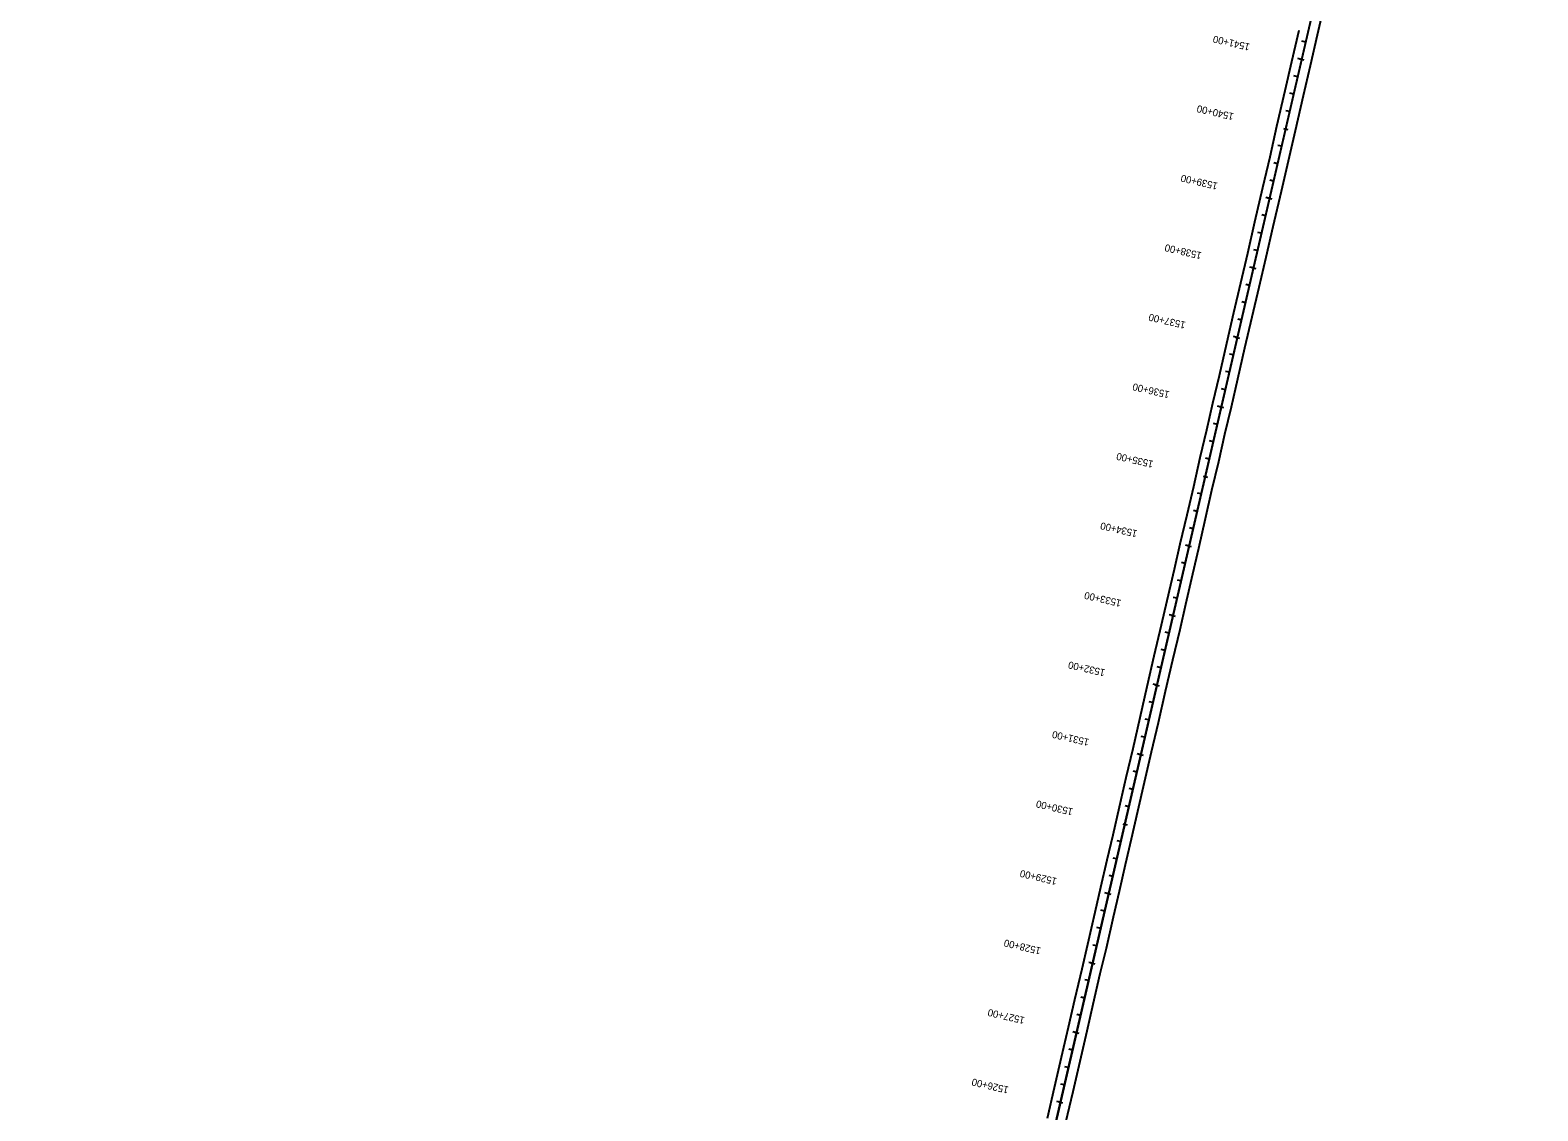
# Model space of a CAD drawing. Extents: x 21596470 to 21601942, y 8263806 to 8275912.
# Drawn here: x 21596601 to 21598714, y 8272882 to 8274396 of the extents above; entities that cross this region are included whole.
import ezdxf

# ---------------------------------------------------------------- set-up
doc = ezdxf.new("R2010")
doc.units = 0
for name, color, linetype in [('Level 1', 7, 'Continuous'), ('Level 20', 7, 'Continuous'), ('SurTxtLeaderLine', 7, 'Continuous'), ('SurTxtSurveyInformation', 7, 'Continuous'), ('wetNoteSoil', 7, 'Continuous')]:
    doc.layers.add(name, color=color, linetype=linetype)

msp = doc.modelspace()

# ---------------------------------------------------------------- linework, layer by layer
at = {"layer": 'Level 1'}
for p, q in [((21598383.4, 8274355.1), (21598378.1, 8274356.3)), ((21598357.9, 8274258.3), (21598363.9, 8274257)), ((21598338.3, 8274160.2), (21598333, 8274161.5)), ((21598315.8, 8274062.8), (21598310.5, 8274064)), ((21598293.3, 8273965.4), (21598287.9, 8273966.6)), ((21598270.7, 8273867.9), (21598265.4, 8273869.2)), ((21598245.2, 8273771.2), (21598251.2, 8273769.8)), ((21598225.6, 8273673.1), (21598220.3, 8273674.3)), ((21598203.1, 8273575.7), (21598197.8, 8273576.9)), ((21598180.6, 8273478.2), (21598175.3, 8273479.5)), ((21598158, 8273380.8), (21598152.7, 8273382)), ((21598132.5, 8273284.1), (21598138.5, 8273282.7)), ((21598113, 8273186), (21598107.6, 8273187.2)), ((21598090.4, 8273088.5), (21598085.1, 8273089.8)), ((21598067.9, 8272991.1), (21598062.6, 8272992.3)), ((21598045.3, 8272893.7), (21598040, 8272894.9))]:
    msp.add_line(p, q, dxfattribs=at)
at = {"layer": 'Level 20'}
for p, q in [((21596601.4, 8266652.3), (21598714.2, 8275785)), ((21596728.7, 8267202.6), (21598588.8, 8275242.6))]:
    msp.add_line(p, q, dxfattribs=at)
at = {"layer": 'SurTxtLeaderLine'}
msp.add_lwpolyline([(21598052.9, 8272865.9), (21598062.9, 8272908.8), (21598072.7, 8272951.2), (21598082.5, 8272993.7), (21598091.2, 8273031.1), (21598101.1, 8273074.3), (21598109.7, 8273109.6), (21598119.6, 8273153.6), (21598127.9, 8273189.4), (21598136.5, 8273226.8), (21598144.8, 8273262.7), (21598153.6, 8273301.9), (21598163, 8273342.3), (21598172.8, 8273384.6), (21598182.5, 8273425.8), (21598192.6, 8273469.8), (21598202.7, 8273513.7), (21598212.8, 8273556.3), (21598220.9, 8273591.8), (21598230.6, 8273634.4), (21598239.2, 8273670.4), (21598248.5, 8273711.9), (21598257.6, 8273751.3), (21598267, 8273791.7), (21598275.8, 8273830.1), (21598284.7, 8273868.1), (21598293.9, 8273907.3), (21598303.8, 8273951.1), (21598314.1, 8273994.4), (21598323.5, 8274036), (21598333.4, 8274078.2), (21598343.1, 8274120.8), (21598354.9, 8274170.3), (21598364.6, 8274213.1), (21598374.4, 8274255.4), (21598385.8, 8274304.5), (21598395.6, 8274346.4), (21598405.4, 8274389.7), (21598415.4, 8274432)], dxfattribs=at)
at = {"layer": 'SurTxtSurveyInformation'}
msp.add_lwpolyline([(21598027.1, 8272871.6), (21598036.9, 8272914.3), (21598046.9, 8272957), (21598056.6, 8272999), (21598065.6, 8273037.8), (21598075.6, 8273080.9), (21598083.6, 8273115.1), (21598093.8, 8273160.1), (21598102, 8273195.3), (21598110.9, 8273233.6), (21598118.9, 8273268.3), (21598128, 8273307.6), (21598137.5, 8273348.8), (21598146.9, 8273389.6), (21598166.8, 8273476.2), (21598176.7, 8273519.3), (21598187, 8273563), (21598195, 8273597.1), (21598204.9, 8273641), (21598213.2, 8273676.2), (21598222.7, 8273717), (21598232, 8273756.7), (21598241.2, 8273797.3), (21598250.3, 8273836), (21598258.8, 8273873.5), (21598268.1, 8273912.3), (21598278.6, 8273957.7), (21598288.4, 8274000.3), (21598297.9, 8274042), (21598307.7, 8274083.8), (21598317.8, 8274127.3), (21598329, 8274175.7), (21598339, 8274218.6), (21598348.6, 8274261.4), (21598360.3, 8274311.3), (21598369.7, 8274352.2), (21598379.8, 8274396.2)], dxfattribs=at)
at = {"layer": 'wetNoteSoil'}
for p, q in [((21598389.1, 8274379.4), (21598383.7, 8274380.7)), ((21598380.4, 8274355.8), (21598386.4, 8274354.4)), ((21598377.8, 8274330.7), (21598372.5, 8274331.9)), ((21598372.2, 8274306.4), (21598366.8, 8274307.6)), ((21598366.5, 8274282), (21598361.2, 8274283.2)), ((21598357.9, 8274258.3), (21598363.9, 8274257)), ((21598355.3, 8274233.3), (21598349.9, 8274234.5)), ((21598349.6, 8274208.9), (21598344.3, 8274210.2)), ((21598344, 8274184.6), (21598338.7, 8274185.8)), ((21598335.4, 8274160.9), (21598341.3, 8274159.5)), ((21598332.7, 8274135.9), (21598327.4, 8274137.1)), ((21598327.1, 8274111.5), (21598321.8, 8274112.7)), ((21598321.4, 8274087.2), (21598316.1, 8274088.4)), ((21598312.8, 8274063.5), (21598318.8, 8274062.1)), ((21598310.2, 8274038.4), (21598304.9, 8274039.7)), ((21598304.5, 8274014.1), (21598299.2, 8274015.3)), ((21598298.9, 8273989.7), (21598293.6, 8273991)), ((21598290.3, 8273966.1), (21598296.2, 8273964.7)), ((21598287.6, 8273941), (21598282.3, 8273942.2)), ((21598282, 8273916.7), (21598276.7, 8273917.9)), ((21598276.4, 8273892.3), (21598271, 8273893.5)), ((21598267.7, 8273868.6), (21598273.7, 8273867.3)), ((21598265.1, 8273843.6), (21598259.8, 8273844.8)), ((21598259.5, 8273819.2), (21598254.1, 8273820.5)), ((21598253.8, 8273794.9), (21598248.5, 8273796.1)), ((21598245.2, 8273771.2), (21598251.2, 8273769.8)), ((21598242.6, 8273746.2), (21598237.2, 8273747.4)), ((21598236.9, 8273721.8), (21598231.6, 8273723)), ((21598231.3, 8273697.4), (21598226, 8273698.7)), ((21598222.7, 8273673.8), (21598228.6, 8273672.4)), ((21598220, 8273648.7), (21598214.7, 8273650)), ((21598214.4, 8273624.4), (21598209.1, 8273625.6)), ((21598208.7, 8273600), (21598203.4, 8273601.2)), ((21598200.1, 8273576.4), (21598206.1, 8273575)), ((21598197.5, 8273551.3), (21598192.2, 8273552.5)), ((21598191.8, 8273526.9), (21598186.5, 8273528.2)), ((21598186.2, 8273502.6), (21598180.9, 8273503.8)), ((21598177.6, 8273478.9), (21598183.6, 8273477.5)), ((21598174.9, 8273453.9), (21598169.6, 8273455.1)), ((21598169.3, 8273429.5), (21598164, 8273430.8)), ((21598163.7, 8273405.2), (21598158.3, 8273406.4)), ((21598155, 8273381.5), (21598161, 8273380.1)), ((21598152.4, 8273356.5), (21598147.1, 8273357.7)), ((21598146.8, 8273332.1), (21598141.4, 8273333.3)), ((21598141.1, 8273307.7), (21598135.8, 8273309)), ((21598132.5, 8273284.1), (21598138.5, 8273282.7)), ((21598129.9, 8273259), (21598124.5, 8273260.3)), ((21598124.2, 8273234.7), (21598118.9, 8273235.9)), ((21598118.6, 8273210.3), (21598113.3, 8273211.5)), ((21598110, 8273186.6), (21598115.9, 8273185.3)), ((21598107.3, 8273161.6), (21598102, 8273162.8)), ((21598101.7, 8273137.2), (21598096.4, 8273138.5)), ((21598096, 8273112.9), (21598090.7, 8273114.1)), ((21598087.4, 8273089.2), (21598093.4, 8273087.8)), ((21598084.8, 8273064.2), (21598079.5, 8273065.4)), ((21598079.1, 8273039.8), (21598073.8, 8273041)), ((21598073.5, 8273015.5), (21598068.2, 8273016.7)), ((21598064.9, 8272991.8), (21598070.9, 8272990.4)), ((21598062.2, 8272966.7), (21598056.9, 8272968)), ((21598056.6, 8272942.4), (21598051.3, 8272943.6)), ((21598051, 8272918), (21598045.7, 8272919.3)), ((21598042.4, 8272894.4), (21598048.3, 8272893))]:
    msp.add_line(p, q, dxfattribs=at)

# ---------------------------------------------------------------- texts
at = {"layer": 'Level 1'}
for s, p in [('1540+00', (21598288.9, 8274279.4)), ('1535+00', (21598176.2, 8273792.3)), ('1530+00', (21598063.6, 8273305.2))]:
    msp.add_text(s, height=10.02, rotation=166.974, dxfattribs=at).set_placement(p)
at = {"layer": 'wetNoteSoil'}
for s, p in [('1541+00', (21598311.5, 8274376.9)), ('1540+00', (21598288.9, 8274279.4)), ('1539+00', (21598266.4, 8274182)), ('1538+00', (21598243.9, 8274084.6)), ('1537+00', (21598221.3, 8273987.2)), ('1536+00', (21598198.8, 8273889.7)), ('1535+00', (21598176.2, 8273792.3)), ('1534+00', (21598153.7, 8273694.9)), ('1533+00', (21598131.2, 8273597.4)), ('1532+00', (21598108.6, 8273500)), ('1531+00', (21598086.1, 8273402.6)), ('1530+00', (21598063.6, 8273305.2)), ('1529+00', (21598041, 8273207.7)), ('1528+00', (21598018.5, 8273110.3)), ('1527+00', (21597995.9, 8273012.9)), ('1526+00', (21597973.4, 8272915.5))]:
    msp.add_text(s, height=10.02, rotation=166.974, dxfattribs=at).set_placement(p)

doc.saveas('drawing.dxf')
